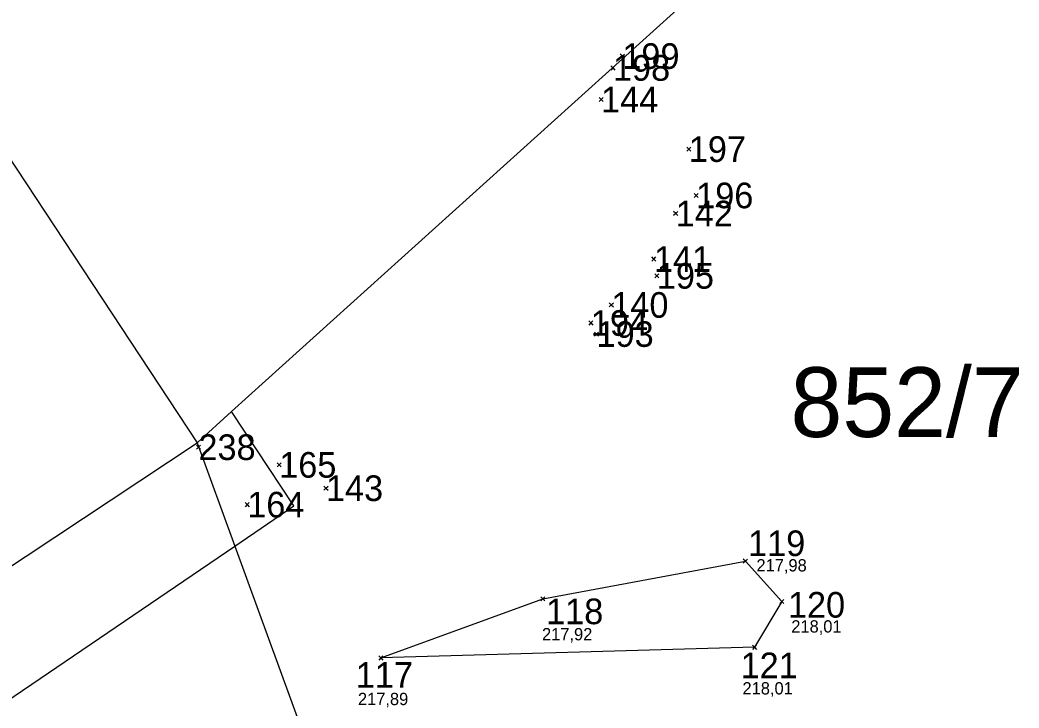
# Model space of a CAD drawing. Extents: x -711879 to -711361, y -1048782 to -1048177.
# Drawn here: x -711669.86 to -711645.5, y -1048541.72 to -1048524.94 of the extents above; entities that cross this region are included whole.
import ezdxf

# ---------------------------------------------------------------- set-up
doc = ezdxf.new("R2010")
doc.units = 0
for name, color, linetype in [('body', 7, 'Continuous'), ('kresba', 7, 'Continuous'), ('Vrstva 1', 7, 'Continuous'), ('Vrstva 14', 7, 'Continuous'), ('Vrstva 2', 7, 'Continuous'), ('Vrstva 20', 7, 'Continuous'), ('Vrstva 41', 7, 'Continuous'), ('výšky', 7, 'Continuous')]:
    doc.layers.add(name, color=color, linetype=linetype)

msp = doc.modelspace()

# ---------------------------------------------------------------- linework, layer by layer
at = {"layer": 'kresba'}
msp.add_lwpolyline([(-711661.06, -1048540.5), (-711657.11, -1048539.06), (-711652.17, -1048538.14), (-711651.28, -1048539.12), (-711651.95, -1048540.24)], close=True, dxfattribs=at)
at = {"layer": 'Vrstva 1'}
for p, q in [((-711653.47, -1048524.35), (-711664.7, -1048534.49)), ((-711671.8, -1048525.77), (-711665.54, -1048535.25)), ((-711664.7, -1048534.49), (-711665.54, -1048535.25)), ((-711683.36, -1048547.06), (-711665.54, -1048535.25)), ((-711665.54, -1048535.25), (-711664.62, -1048537.77)), ((-711664.62, -1048537.77), (-711660.61, -1048548.8))]:
    msp.add_line(p, q, dxfattribs=at)
at = {"layer": 'Vrstva 2'}
for p, q in [((-711663.18, -1048536.79), (-711664.7, -1048534.49)), ((-711664.62, -1048537.77), (-711663.18, -1048536.79)), ((-711692.52, -1048556.74), (-711664.62, -1048537.77))]:
    msp.add_line(p, q, dxfattribs=at)
at = {"layer": 'Vrstva 20'}
for p, q in [((-711655.17, -1048525.82), (-711655.22, -1048525.77)), ((-711655.17, -1048525.82), (-711655.22, -1048525.87)), ((-711655.17, -1048525.82), (-711655.12, -1048525.77)), ((-711655.17, -1048525.82), (-711655.12, -1048525.87)), ((-711655.4, -1048526.11), (-711655.45, -1048526.06)), ((-711655.4, -1048526.11), (-711655.45, -1048526.16)), ((-711655.4, -1048526.11), (-711655.35, -1048526.06)), ((-711655.4, -1048526.11), (-711655.35, -1048526.16)), ((-711655.69, -1048526.88), (-711655.74, -1048526.83)), ((-711655.69, -1048526.88), (-711655.74, -1048526.93)), ((-711655.69, -1048526.88), (-711655.64, -1048526.83)), ((-711655.69, -1048526.88), (-711655.64, -1048526.93)), ((-711653.55, -1048528.09), (-711653.6, -1048528.04)), ((-711653.55, -1048528.09), (-711653.6, -1048528.14)), ((-711653.55, -1048528.09), (-711653.5, -1048528.04)), ((-711653.55, -1048528.09), (-711653.5, -1048528.14)), ((-711653.37, -1048529.22), (-711653.42, -1048529.17)), ((-711653.37, -1048529.22), (-711653.42, -1048529.27)), ((-711653.37, -1048529.22), (-711653.32, -1048529.17)), ((-711653.37, -1048529.22), (-711653.32, -1048529.27)), ((-711653.87, -1048529.66), (-711653.92, -1048529.61)), ((-711653.87, -1048529.66), (-711653.92, -1048529.71)), ((-711653.87, -1048529.66), (-711653.82, -1048529.61)), ((-711653.87, -1048529.66), (-711653.82, -1048529.71)), ((-711654.4, -1048530.77), (-711654.45, -1048530.72)), ((-711654.4, -1048530.77), (-711654.45, -1048530.82)), ((-711654.4, -1048530.77), (-711654.35, -1048530.72)), ((-711654.4, -1048530.77), (-711654.35, -1048530.82)), ((-711654.33, -1048531.18), (-711654.38, -1048531.13)), ((-711654.33, -1048531.18), (-711654.38, -1048531.23)), ((-711654.33, -1048531.18), (-711654.28, -1048531.13)), ((-711654.33, -1048531.18), (-711654.28, -1048531.23)), ((-711655.44, -1048531.89), (-711655.49, -1048531.84)), ((-711655.44, -1048531.89), (-711655.49, -1048531.94)), ((-711655.44, -1048531.89), (-711655.39, -1048531.84)), ((-711655.44, -1048531.89), (-711655.39, -1048531.94)), ((-711655.94, -1048532.33), (-711655.99, -1048532.28)), ((-711655.94, -1048532.33), (-711655.99, -1048532.38)), ((-711655.94, -1048532.33), (-711655.89, -1048532.28)), ((-711655.94, -1048532.33), (-711655.89, -1048532.38)), ((-711655.8, -1048532.6), (-711655.85, -1048532.55)), ((-711655.8, -1048532.6), (-711655.85, -1048532.65)), ((-711655.8, -1048532.6), (-711655.75, -1048532.55)), ((-711655.8, -1048532.6), (-711655.75, -1048532.65)), ((-711665.51, -1048535.36), (-711665.56, -1048535.31)), ((-711665.51, -1048535.36), (-711665.56, -1048535.41)), ((-711665.51, -1048535.36), (-711665.46, -1048535.31)), ((-711665.51, -1048535.36), (-711665.46, -1048535.41)), ((-711663.54, -1048535.79), (-711663.59, -1048535.74)), ((-711663.54, -1048535.79), (-711663.59, -1048535.84)), ((-711663.54, -1048535.79), (-711663.49, -1048535.74)), ((-711663.54, -1048535.79), (-711663.49, -1048535.84)), ((-711662.4, -1048536.36), (-711662.45, -1048536.31)), ((-711662.4, -1048536.36), (-711662.45, -1048536.41)), ((-711662.4, -1048536.36), (-711662.35, -1048536.31)), ((-711662.4, -1048536.36), (-711662.35, -1048536.41)), ((-711664.32, -1048536.76), (-711664.37, -1048536.71)), ((-711664.32, -1048536.76), (-711664.37, -1048536.81)), ((-711664.32, -1048536.76), (-711664.27, -1048536.71)), ((-711664.32, -1048536.76), (-711664.27, -1048536.81)), ((-711652.17, -1048538.14), (-711652.22, -1048538.09)), ((-711652.17, -1048538.14), (-711652.12, -1048538.09)), ((-711652.17, -1048538.14), (-711652.22, -1048538.19)), ((-711652.17, -1048538.14), (-711652.12, -1048538.19)), ((-711657.11, -1048539.06), (-711657.16, -1048539.01)), ((-711657.11, -1048539.06), (-711657.16, -1048539.11)), ((-711657.11, -1048539.06), (-711657.06, -1048539.01)), ((-711657.11, -1048539.06), (-711657.06, -1048539.11)), ((-711651.28, -1048539.12), (-711651.33, -1048539.07)), ((-711651.28, -1048539.12), (-711651.23, -1048539.07)), ((-711651.28, -1048539.12), (-711651.33, -1048539.17)), ((-711651.28, -1048539.12), (-711651.23, -1048539.17)), ((-711651.95, -1048540.24), (-711652, -1048540.19)), ((-711651.95, -1048540.24), (-711652, -1048540.29)), ((-711651.95, -1048540.24), (-711651.9, -1048540.19)), ((-711651.95, -1048540.24), (-711651.9, -1048540.29)), ((-711661.06, -1048540.5), (-711661.11, -1048540.45)), ((-711661.06, -1048540.5), (-711661.11, -1048540.55)), ((-711661.06, -1048540.5), (-711661.01, -1048540.45)), ((-711661.06, -1048540.5), (-711661.01, -1048540.55))]:
    msp.add_line(p, q, dxfattribs=at)
at = {"layer": 'Vrstva 41'}
for p, q in [((-711655.17, -1048525.82), (-711655.17, -1048525.82)), ((-711655.4, -1048526.11), (-711655.4, -1048526.11)), ((-711655.69, -1048526.88), (-711655.69, -1048526.88)), ((-711653.55, -1048528.09), (-711653.55, -1048528.09)), ((-711653.37, -1048529.22), (-711653.37, -1048529.22)), ((-711653.87, -1048529.66), (-711653.87, -1048529.66)), ((-711654.4, -1048530.77), (-711654.4, -1048530.77)), ((-711654.33, -1048531.18), (-711654.33, -1048531.18)), ((-711655.44, -1048531.89), (-711655.44, -1048531.89)), ((-711655.94, -1048532.33), (-711655.94, -1048532.33)), ((-711655.8, -1048532.6), (-711655.8, -1048532.6)), ((-711665.51, -1048535.36), (-711665.51, -1048535.36)), ((-711663.54, -1048535.79), (-711663.54, -1048535.79)), ((-711662.4, -1048536.36), (-711662.4, -1048536.36)), ((-711664.32, -1048536.76), (-711664.32, -1048536.76)), ((-711652.17, -1048538.14), (-711652.17, -1048538.14)), ((-711657.11, -1048539.06), (-711657.11, -1048539.06)), ((-711651.28, -1048539.12), (-711651.28, -1048539.12)), ((-711651.95, -1048540.24), (-711651.95, -1048540.24)), ((-711661.06, -1048540.5), (-711661.06, -1048540.5))]:
    msp.add_line(p, q, dxfattribs=at)

# ---------------------------------------------------------------- texts
at = {"layer": 'body'}
for s, p in [('199', (-711655.17, -1048526.133)), ('198', (-711655.4, -1048526.422)), ('144', (-711655.69, -1048527.193)), ('197', (-711653.55, -1048528.402)), ('196', (-711653.37, -1048529.532)), ('142', (-711653.87, -1048529.973)), ('141', (-711654.4, -1048531.083)), ('195', (-711654.33, -1048531.493)), ('140', (-711655.44, -1048532.203)), ('194', (-711655.94, -1048532.643)), ('193', (-711655.8, -1048532.912)), ('238', (-711665.51, -1048535.672)), ('165', (-711663.54, -1048536.103)), ('143', (-711662.4, -1048536.672)), ('164', (-711664.32, -1048537.073)), ('119', (-711652.104, -1048538.015)), ('118', (-711657.03, -1048539.676)), ('120', (-711651.132, -1048539.516)), ('121', (-711652.287, -1048540.993)), ('117', (-711661.672, -1048541.227))]:
    msp.add_text(s, height=0.625, dxfattribs=at).set_placement(p)
at = {"layer": 'Vrstva 14'}
msp.add_text('852/7', height=1.7, dxfattribs=at).set_placement((-711651.07, -1048535.11))
at = {"layer": 'výšky'}
for s, p in [('217,98', (-711651.9, -1048538.39)), ('217,92', (-711657.13, -1048540.07)), ('218,01', (-711651.05, -1048539.88)), ('218,01', (-711652.24, -1048541.39)), ('217,89', (-711661.62, -1048541.65))]:
    msp.add_text(s, height=0.3, dxfattribs=at).set_placement(p)

doc.saveas('drawing.dxf')
